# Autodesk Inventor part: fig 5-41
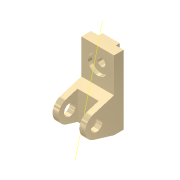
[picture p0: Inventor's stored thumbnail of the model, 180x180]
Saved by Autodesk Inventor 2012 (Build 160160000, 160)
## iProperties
Shininess: 65.0
Angle Display Precision: 2
Document Length Units: 11269
Document Angle Units: 11279
Document Time Units: 11290
Document Mass Units: 11283
Document Length Units Precision: 3
Document Angle Units Precision: 2
Created: 2001-11
Part Number: fig 5-41
Document SubType Name: Modeling
Designer: Renu Muthoo
Density: 1 g/cm^3
Material: Default
Density: 0.0
Volumn: 0.0
Area: 0.0
PropertySet Name: Model Information
Control State: 0
Master: False
Checked Out: False
Author: Renu Muthoo
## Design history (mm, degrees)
node "Sketch1"
sketch "Sketch2"
  geometry: L1 (33.257, 104.664)-(33.257, -75.336); L2 (33.257, -75.336)-(8.257, -75.336); L3 (8.257, -75.336)-(-45.451, -59.045); L4 (-45.451, -1.628)-(8.257, 14.664); L5 (8.257, 14.664)-(8.257, 104.664); L6 (8.257, 104.664)-(33.257, 104.664); C1 r 15 at (-36.743, -30.336); A1 r 30 centre (-36.743, -30.336) between (-45.451, -1.628) and (-45.451, -59.045)
  constraints: 12 end point, 2 centre point, 2 equal length, 2 parallel, 2 point on circle, 2 tangent, 1 coincident, 1 perpendicular, 1 vertical
  dimensions: "d0" = 180 distance of L1.start L1.end; "d1" = 30 radius of A1; "d2" = 25 distance of L5.end L1.start; "d3" = 45 distance from line of L2 A1.centre; "d4" = 70 distance from line of L1 A1.centre; "d5" = 30 diameter of C1
extrude "Extrusion1" new body sketch "Sketch2" distance "d6" = 85; taper "d7" = 0 deg
workplane "Work Plane1"
sketch "Sketch3"
  geometry: L1 (15, 62.364)-(70, 62.364); L2 (70, 62.364)-(70, -52.386); L3 (70, -52.386)-(15, -52.386); L4 (15, -52.386)-(15, 62.364); L5 (0, -45)-(0, -28.708) reference
  constraints: 8 end point, 2 parallel, 1 horizontal, 1 perpendicular
  dimensions: "d8" = 55 distance of L1.start L1.end; "d9" = 15 distance between parallel lines of L5 L4
extrude "Extrusion2" cut sketch "Sketch3" distance "d10" = 50; taper "d11" = 0 deg
sketch "Sketch4"
  geometry: L1 (0, 25)-(85, 25) reference; L2 (0, 0)-(0, 25) reference; L3 (20, 25)-(65, 25); L4 (65, 25)-(65, 35); L5 (65, 35)-(20, 35); L6 (20, 35)-(20, 25)
  constraints: 8 end point, 2 parallel, 1 horizontal, 1 perpendicular, 1 point on line
  dimensions: "d12" = 45 distance of L4.end L5.end; "d13" = 10 distance of L3.end L4.end; "d14" = 20 distance between parallel lines of L2 L6
extrude "Extrusion3" join sketch "Sketch4" stored distance "d15" = 50; taper "d16" = 0 deg
sketch "Sketch5"
  geometry: L1 (85, 0)-(85, 90) reference; L2 (0, 90)-(85, 90) reference; 1 further point
  dimensions: "d17" = 42 distance from line of L2 point (42.5, 48); "d18" = 42.5 distance from line of L1 point (42.5, 48)
hole "Hole1" sketch "Sketch5" at (42.5, 48) diameter "d19" = 20; stored, may be unused: countersink angle "d23" = 82 deg, drill point angle "d25" = 118 deg; dims "d20" = 6, "d21" = 50, "d22" = 10, "d24" = 8
workaxis "Work Axis1"
body "Solid1"
